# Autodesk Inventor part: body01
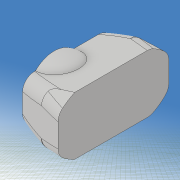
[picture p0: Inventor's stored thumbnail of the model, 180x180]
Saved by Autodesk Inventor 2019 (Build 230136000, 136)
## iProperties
Created: 2020-12
Part Number: body01
Material: 一般
Document SubType Name: Modeling
Designer: kikut
Density: 1 g/cm^3
Appearance: 既定
Mass: 87.6477 g
Surface Area: 156.124 cm^2
Volume: 87.6477 cm^3
Author: kikut
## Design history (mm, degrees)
sketch "スケッチ1"
  geometry: L1 (-100, -20)-(100, -20); L2 (100, -20)-(100, 20); L3 (100, 20)-(-100, 20); L4 (-100, 20)-(-100, -20); L5 (-100, -20)-(100, 20); L6 (100, -20)-(-100, 20); 1 further point
  constraints: 12 end point, 2 midpoint, 2 parallel, 1 horizontal, 1 perpendicular
  dimensions: "d0" = 40 distance of L3.end L1.start; "d1" = 200 distance of L2.end L3.end
extrude "押し出し1" new body sketch "スケッチ1" stored distance "d2" = 60; taper "d3" = 0 deg
sketch "スケッチ2"
  geometry: L1 (0, -60)-(0, 0) reference; L2 (200, -60)-(200, 0) reference; L3 (0, 0)-(200, 0) reference; L4 (200, -60)-(0, -60) reference; L5 (0, -26)-(0, -32); L6 (194, -10)-(194, -13); L7 (194, -13)-(174, -33); L8 (174, -33)-(200, -58); L9 (-20, 20)-(220, 20); L10 (220, 20)-(220, -100); L11 (220, -100)-(-20, -100); L12 (-20, -100)-(-20, 20); 12 further points
  constraints: 16 end point, 4 point on line, 2 parallel, 2 vertical, 1 horizontal, 1 perpendicular, 14 other
  dimensions: "d4" = 32 distance from line of point (32, -12) L1; "d5" = 50 horizontal distance of point (32, -12) point (82, -11); "d6" = 50 horizontal distance of point (132, -17) point (82, -11); "d7" = 12 distance from line of point (32, -12) L3; "d8" = 11 distance from line of point (82, -11) L3; "d10" = 17 distance from line of point (132, -17) L3; "d11" = 26 distance from line of L5.start L3; "d12" = 0 distance from line of point (200, -60) L4; "d13" = 28 distance from line of L5.end L4; "d14" = 12 distance from line of point (28, -48) L4; "d15" = 10 distance from line of point (80, -50) L4; "d16" = 16 distance from line of point (130, -44) L4; "d17" = 28 distance from line of point (28, -48) L1; "d19" = 50 horizontal distance of point (130, -44) point (80, -50); "d20" = 80 distance from line of point (80, -50) L1; "d21" = 6 distance from line of L6.start L2; "d22" = 36 distance from line of point (164, -24) L2; "d23" = 24 distance from line of point (176, -20) L2; "d24" = 10 distance from line of L6.start L3; "d25" = 20 distance from line of point (176, -20) L3; "d26" = 24 distance from line of point (164, -24) L3; "d27" = 40 distance from line of point (160, -40) L2; "d28" = 25 distance from line of point (175, -47.5) L2; "d29" = 12.5 distance from line of point (175, -47.5) L4; "d30" = 20 distance from line of L4 point (160, -40); "d31" = 3 distance of L6.start L6.end; "d32" = 33 distance from line of L7.end L3; "d33" = 26 distance from line of L7.end L2; "d34" = 2 distance of L8.end L2.start; "d35" = 120 distance of L11.end L9.start; "d36" = 240 distance of L10.end L11.end; "d37" = 20 distance between parallel lines of L1 L12; "d38" = 20 distance between parallel lines of L3 L9
extrude "押し出し2" cut sketch "スケッチ2" extent not by distance; stored distance "d39" = 0.02; taper "d40" = 0 deg
sketch "スケッチ8"
  geometry: L1 (-100, -20)-(-100, 20) reference; L2 (100, 20)-(100, -20) reference; L3 (-142.805, 0)-(142.831, 0) reference; L4 (110, 30)-(-110, 30); L5 (-110, 30)-(-110, -30); L6 (-110, -30)-(110, -30); L7 (110, -30)-(110, 30); L8 (110, 30)-(-110, -30); L9 (-110, 30)-(110, -30); L10 (-100, -2)-(-100, 2); L11 (100, -3)-(100, 3); 7 further points
  constraints: 16 end point, 4 point on line, 2 midpoint, 2 parallel, 2 perpendicular, 1 collinear, 1 horizontal, 10 other
  dimensions: "d93" = 2 vertical distance of point (0, 0) L10.end; "d94" = 2 vertical distance of L10.start point (0, 0); "d95" = 35 distance from line of point (-65, -10) L1; "d96" = 0 horizontal distance of point (-65, 10) point (-65, -10); "d97" = 10 vertical distance of point (0, 0) point (-65, -10); "d98" = 10 vertical distance of point (-65, 10) point (0, 0); "d99" = 100 distance from line of point (0, -10) L1; "d100" = 0 horizontal distance of point (0, 10) point (0, -10); "d101" = 10 distance of point (0, -10) point (0, 0); "d102" = 10 distance of point (0, 0) point (0, 10); "d103" = 160 distance from line of point (60, -4) L1; "d104" = 0 horizontal distance of point (60, 4) point (60, -4); "d105" = 4 distance from line of L3 point (60, -4); "d106" = 4 distance from line of L3 point (60, 4); "d107" = 3 distance from line of L11.start L3; "d108" = 3 distance from line of L11.end L3; "d109" = 220 distance of L5.end L6.end; "d110" = 60 distance of L4.end L5.end
extrude "押し出し6" cut sketch "スケッチ8" extent not by distance; stored distance "d111" = 10; taper "d112" = 0 deg
sketch "スケッチ9" dims "d113" = 20, "d114" = 12
  geometry: L1 (-29, -18)-(21, -18); L2 (21, -18)-(21, 22); L3 (21, 22)-(-29, 22); L4 (-29, 22)-(-29, -18); L5 (-29, -18)-(21, 22); L6 (21, -18)-(-29, 22); 2 further points; 1 other entity
  constraints: 12 end point, 2 midpoint, 2 parallel, 1 coincident, 1 horizontal, 1 perpendicular, 2 other
  dimensions: "d115" = 50 distance of L2.end L3.end; "d116" = 40 distance of L1.end L2.end
extrude "押し出し7" cut sketch "スケッチ9" distance "d117" = 150; taper "d118" = 0 deg
fillet "フィレット4" dims "d119" = 4
fillet "フィレット5" dims "d120" = 4
fillet "フィレット6" dims "d121" = 2
node "作業平面2"
sketch "スケッチ10"
  geometry: L1 (0, -41.439)-(0, 38.458) reference; L2 (141.833, 0)-(-140.631, 0) reference; L3 (82.55, 12.983)-(81.45, -4.983); A1 r 9 centre (82, 4) between (82.55, 12.983) and (81.45, -4.983); 1 further point
  constraints: 2 end point, 2 point on circle, 1 centre point
  dimensions: "d123" = 82 distance from line of L1 A1.centre; "d124" = 4 distance from line of L2 A1.centre; "d125" = 9 radius of A1; "d126" = 180 deg dimension on A1.centre L3.end L3.start; "d127" = 90 deg dimension on L3.end point (0, 0) A1.centre
revolve "回転1" sketch "スケッチ10" stored, may be unused: angle "d128" = 90 deg
mirror "ミラー1"
sketch "スケッチ11"
  geometry: L1 (85, 30)-(70, 30); L2 (70, 30)-(70, -30); L3 (70, -30)-(85, -30); L4 (85, -30)-(85, 30); L5 (0, -40.648)-(0, 34.486) reference; L6 (140.69, 0)-(-139.196, 0) reference; L7 (120, 53.792)-(-120, 53.792); L8 (-120, 53.792)-(-120, -46.208); L9 (-120, -46.208)-(120, -46.208); L10 (120, -46.208)-(120, 53.792); 1 further point
  constraints: 16 end point, 4 parallel, 2 horizontal, 2 perpendicular, 2 other
  dimensions: "d129" = 70 distance between parallel lines of L5 L2; "d130" = 15 distance of L1.start L1.end; "d131" = 60 distance of L3.end L1.start; "d132" = 100 distance of L9.end L7.start; "d133" = 240 distance of L7.start L7.end
extrude "押し出し8" cut sketch "スケッチ11" stored distance "d134" = 40; taper "d135" = 0 deg
node "ソリッド1"
other parameters: "d122" = -1
